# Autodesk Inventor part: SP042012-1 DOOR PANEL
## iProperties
Created: 2012-04
Part Number: SP042012-1 DOOR PANEL
Material: Polycarbonate, Clear
Document SubType Name: Modeling
Designer: Administrator
Mass: 3512.53 g
Surface Area: 10639.5 cm^2
Volume: 2927.11 cm^3
Density: 1.2 g/cm^3
Author: Administrator
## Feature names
1. Extrusion1
2. Hole1
